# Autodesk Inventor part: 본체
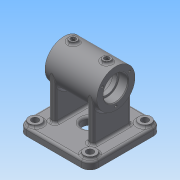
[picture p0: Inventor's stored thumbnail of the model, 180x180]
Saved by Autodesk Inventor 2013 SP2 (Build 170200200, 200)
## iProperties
Created: 2025-10
Part Number: 본체
Material: Generic
Document SubType Name: Modeling
Designer: 601
Density: 1 g/cm^3
Author: 601
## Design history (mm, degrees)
sketch "스케치1"
  geometry: L1 (47, -47)-(-47, -47); L2 (-47, -47)-(-47, 47); L3 (-47, 47)-(47, 47); L4 (47, 47)-(47, -47); L5 (47, -47)-(-47, 47); L6 (-47, -47)-(47, 47); L7 (-21, 22)-(-21, -22); L8 (-29, 22)-(-29, -22); L9 (0, -47)-(0, 47); L10 (21, 22)-(21, -22); L11 (29, 22)-(29, -22); L12 (-26, 25)-(-24, 25); L13 (24, 25)-(26, 25); L14 (24, -25)-(26, -25); L15 (-26, -25)-(-24, -25); C1 r 10 at (0, 0); A1 r 3 centre (-26, 22) between (-26, 25) and (-29, 22); A2 r 3 centre (-24, 22) between (-21, 22) and (-24, 25); A3 r 3 centre (-26, -22) between (-29, -22) and (-26, -25); A4 r 3 centre (-24, -22) between (-24, -25) and (-21, -22); A5 r 3 centre (24, -22) between (21, -22) and (24, -25); A6 r 3 centre (26, -22) between (26, -25) and (29, -22); A7 r 3 centre (26, 22) between (29, 22) and (26, 25); A8 r 3 centre (24, 22) between (24, 25) and (21, 22); 9 further points
  constraints: 30 end point, 16 point on circle, 16 point on line, 16 tangent, 9 centre point, 6 equal radius, 6 midpoint, 5 parallel, 4 symmetric about line, 2 perpendicular, 1 collinear, 1 horizontal
  dimensions: "d0" = 94 distance of L2.end L3.end; "d1" = 94 distance of L3.end L1.start; "d67" = 20 diameter of C1; "d150" = 25 distance from line of L12 point (0, 0); "d151" = 8 distance of point (-29, 25) point (-21, 25); "d152" = 42 distance between parallel lines of L7 L10; "d153" = 3 radius of A1; "d154" = 50 distance between parallel lines of L15 L12; "d155" = 3 radius of A3
extrude "돌출1" new body sketch "스케치1" distance "d7" = 10; taper "d8" = 0 deg
sketch "스케치2"
  geometry: L1 (-47, 0)-(-47, 10) reference; L2 (-47, 10)-(47, 10) reference; L3 (47, 10)-(47, 0) reference; L4 (47, 0)-(-47, 0) reference; L5 (-34, 66)-(34, 66); L6 (-34, 66)-(-34, 50); L7 (-34, 41)-(34, 41); L8 (34, 41)-(34, 50); L9 (-34, 50)-(-22.3, 50); L10 (-22, 50.3)-(-22, 52.5); L11 (-22, 52.5)-(-16.258, 52.5); L12 (-16.258, 52.5)-(-5.696, 46.402); L13 (-4.196, 46)-(4.196, 46); L14 (5.696, 46.402)-(16.258, 52.5); L15 (16.258, 52.5)-(22, 52.5); L16 (22, 52.5)-(22, 50.3); L17 (22.3, 50)-(34, 50); L18 (-34, 50)-(-34, 41); L19 (34, 50)-(34, 66); A1 r 0.3 centre (-22.3, 50.3) between (-22.3, 50) and (-22, 50.3); A2 r 0.3 centre (22.3, 50.3) between (22, 50.3) and (22.3, 50); A3 r 3 centre (-4.196, 49) between (-5.696, 46.402) and (-4.196, 46); A4 r 3 centre (4.196, 49) between (4.196, 46) and (5.696, 46.402); 8 further points
  constraints: 30 end point, 8 point on circle, 8 point on line, 8 tangent, 7 perpendicular, 6 parallel, 4 centre point, 4 vertical alignment, 3 midpoint, 2 equal radius
  dimensions: "d9" = 66 vertical distance of L3.end L5.end; "d10" = 68 distance of L5.start L5.end; "d11" = 50 diameter of L7 L5; "d12" = 12 distance of L6.end point (-22, 50); "d13" = 12 distance of point (22, 50) L8.end; "d14" = 10 distance of point (-5, 46) point (5, 46); "d15" = 30 deg angle of L5 L12; "d16" = 30 deg angle of L5 L14; "d17" = 32 diameter of L9 L5; "d18" = 27 diameter of L11 L5; "d19" = 40 diameter of L13 L5; "d20" = 32 diameter of L17 L5; "d22" = 27 diameter of L15 L5; "d23" = 0.3 radius of A1; "d24" = 3 radius of A3
revolve "회전1" sketch "스케치2" stored, may be unused: angle "d25" = 90 deg
extrude "돌출2" join sketch "스케치1" stored distance "d26" = 66.25; taper "d27" = 0 deg
node "작업 평면1"
sketch "스케치3"
  geometry: L1 (34, -25)-(34, 25) reference; L2 (-34, -25)-(-34, 25) reference; C1 r 5 at (-22, 0); C2 r 5 at (22, 0); 1 further point
  constraints: 2 centre point, 2 horizontal alignment
  dimensions: "d29" = 10 diameter of C1; "d30" = 10 diameter of C2; "d31" = 12 distance from line of C2.centre L1; "d32" = 12 distance from line of C1.centre L2
extrude "돌출3" join sketch "스케치3" stored distance "d33" = 66.25; taper "d34" = 0 deg
hole "구멍1" diameter "d37" = 5.188; stored, may be unused: countersink angle "d41" = 90 deg, drill point angle "d43" = 0 deg; dims "d35" = 10, "d36" = 10, "d38" = 6, "d39" = 6.6, "d40" = 2, "d42" = 8
hole "구멍2" diameter "d46" = 5.188; stored, may be unused: countersink angle "d50" = 90 deg, drill point angle "d52" = 0 deg; dims "d44" = 10, "d45" = 10, "d47" = 6, "d48" = 6.6, "d49" = 2, "d51" = 8
extrude "돌출4" cut sketch "스케치1" distance "d68" = 10; taper "d69" = 0 deg
fillet "모깎기1" dims "d70" = 11
sketch "스케치5"
  geometry: C1 r 8 at (-36, 36); C2 r 8 at (36, 36); C3 r 8 at (36, -36); C4 r 8 at (-36, -36); A1 r 11 centre (-36, 36) between (-36, 47) and (-47, 36) reference; A2 r 11 centre (-36, -36) between (-47, -36) and (-36, -47) reference; A3 r 11 centre (36, -36) between (36, -47) and (47, -36) reference; A4 r 11 centre (36, 36) between (47, 36) and (36, 47) reference
  constraints: 4 centre point, 4 coincident
  dimensions: "d71" = 16 diameter of C1; "d73" = 16 diameter of C2; "d74" = 16 diameter of C3; "d75" = 16 diameter of C4
extrude "돌출5" join sketch "스케치5" distance "d76" = 3; taper "d77" = 0 deg
hole "구멍4" diameter "d80" = 9; stored, may be unused: countersink angle "d84" = 90 deg, drill point angle "d86" = 0 deg; dims "d78" = 10, "d79" = 10, "d81" = 6, "d82" = 4, "d83" = 2, "d85" = 8
hole "구멍5" diameter "d89" = 9; stored, may be unused: countersink angle "d93" = 90 deg, drill point angle "d95" = 0 deg; dims "d87" = 10, "d88" = 10, "d90" = 6, "d91" = 4, "d92" = 2, "d94" = 8
hole "구멍6" diameter "d98" = 9; stored, may be unused: countersink angle "d102" = 90 deg, drill point angle "d104" = 0 deg; dims "d96" = 10, "d97" = 10, "d99" = 6, "d100" = 4, "d101" = 2, "d103" = 8
hole "구멍7" diameter "d107" = 9; stored, may be unused: countersink angle "d111" = 90 deg, drill point angle "d113" = 0 deg; dims "d105" = 10, "d106" = 10, "d108" = 6, "d109" = 4, "d110" = 2, "d112" = 8
node "작업 평면3"
sketch "스케치6"
  geometry: L1 (-21.79, 2.742)-(21.79, 2.742); L2 (21.79, 2.742)-(21.79, -2.742); L3 (21.79, -2.742)-(-21.79, -2.742); L4 (-21.79, -2.742)-(-21.79, 2.742); L5 (36, -66)-(-36, -66) reference; L6 (34, -25)-(34, 25) reference; 5 further points
  constraints: 4 midpoint, 1 horizontal alignment, 1 vertical alignment, 2 other
feature "엠보싱1" sketch "스케치6" dims "d0" = 94, "d1" = 94, "d9" = 66, "d10" = 68, "d11" = 50, "d12" = 12, "d13" = 12, "d14" = 10, "d15" = 30 deg, "d16" = 30 deg, "d17" = 32, "d18" = 27, "d19" = 40, "d20" = 32, "d22" = 27, "d23" = 0.3, "d24" = 3, "d67" = 20, "d114" = 0.5, "d115" = 0, "d150" = 25, "d151" = 8, "d152" = 42, "d153" = 3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
chamfer "모따기1" distance "d116" = 1; stored, may be unused: second distance "d117" = 2, angle "d118" = 45 deg
fillet "모깎기2" dims "d119" = 3
fillet "모깎기3" dims "d120" = 3
fillet "모깎기4" dims "d121" = 3
node "작업 평면4"
sketch "스케치7"
  geometry: C1 r 6 at (0, 0); 1 further point
  constraints: 1 centre point, 1 coincident
  dimensions: "d123" = 12 diameter of C1
extrude "돌출6" join sketch "스케치7" stored distance "d124" = 3; taper "d125" = 0 deg
hole "구멍8" diameter "d128" = 5.188; stored, may be unused: countersink angle "d132" = 90 deg, drill point angle "d134" = 0 deg; dims "d126" = 10, "d127" = 10, "d129" = 6, "d130" = 4, "d131" = 2, "d133" = 8
sketch "스케치8"
  geometry: L1 (0, 0)-(0, 20.5); L2 (0, 0)-(-17.754, 10.25); C1 r 17 at (0, 0) reference; A1 r 20.5 centre (0, 0) between (0, 20.5) and (-17.754, 10.25); 2 further points
  constraints: 4 end point, 2 coincident, 2 point on circle, 1 centre point, 1 vertical
  dimensions: "d135" = 41 diameter of A1; "d136" = 60 deg angle of L2 L1
hole "구멍9" sketch "스케치8" at (-17.754, 10.25) diameter "d138" = 3.242; stored, may be unused: countersink angle "d142" = 90 deg, drill point angle "d144" = 118 deg; dims "d139" = 8, "d140" = 4, "d141" = 2, "d143" = 10
fillet "모깎기5" dims "d148" = 3
fillet "모깎기6" dims "d156" = 3
node "솔리드1"
pattern_circular "원형 패턴1" dims angle "d146" = 360 deg
mirror "대칭1"
node "절단 모서리 투영1"
other parameters: "d28" = 94, "d122" = 38
